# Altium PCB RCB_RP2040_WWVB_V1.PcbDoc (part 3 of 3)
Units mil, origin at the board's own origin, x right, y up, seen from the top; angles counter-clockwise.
Board outline 1250.1 x 2647.64 mil, 10 copper layers (L01-TOP, L02-GND, L03-SIG, L04-GND, L05-PWR, L06-PWR, L07-GND, L08-SIG, L09-GND, L10-BOT), stack 62.1 mil thick; 224 components, 123 nets, 635 pads, 542 vias.
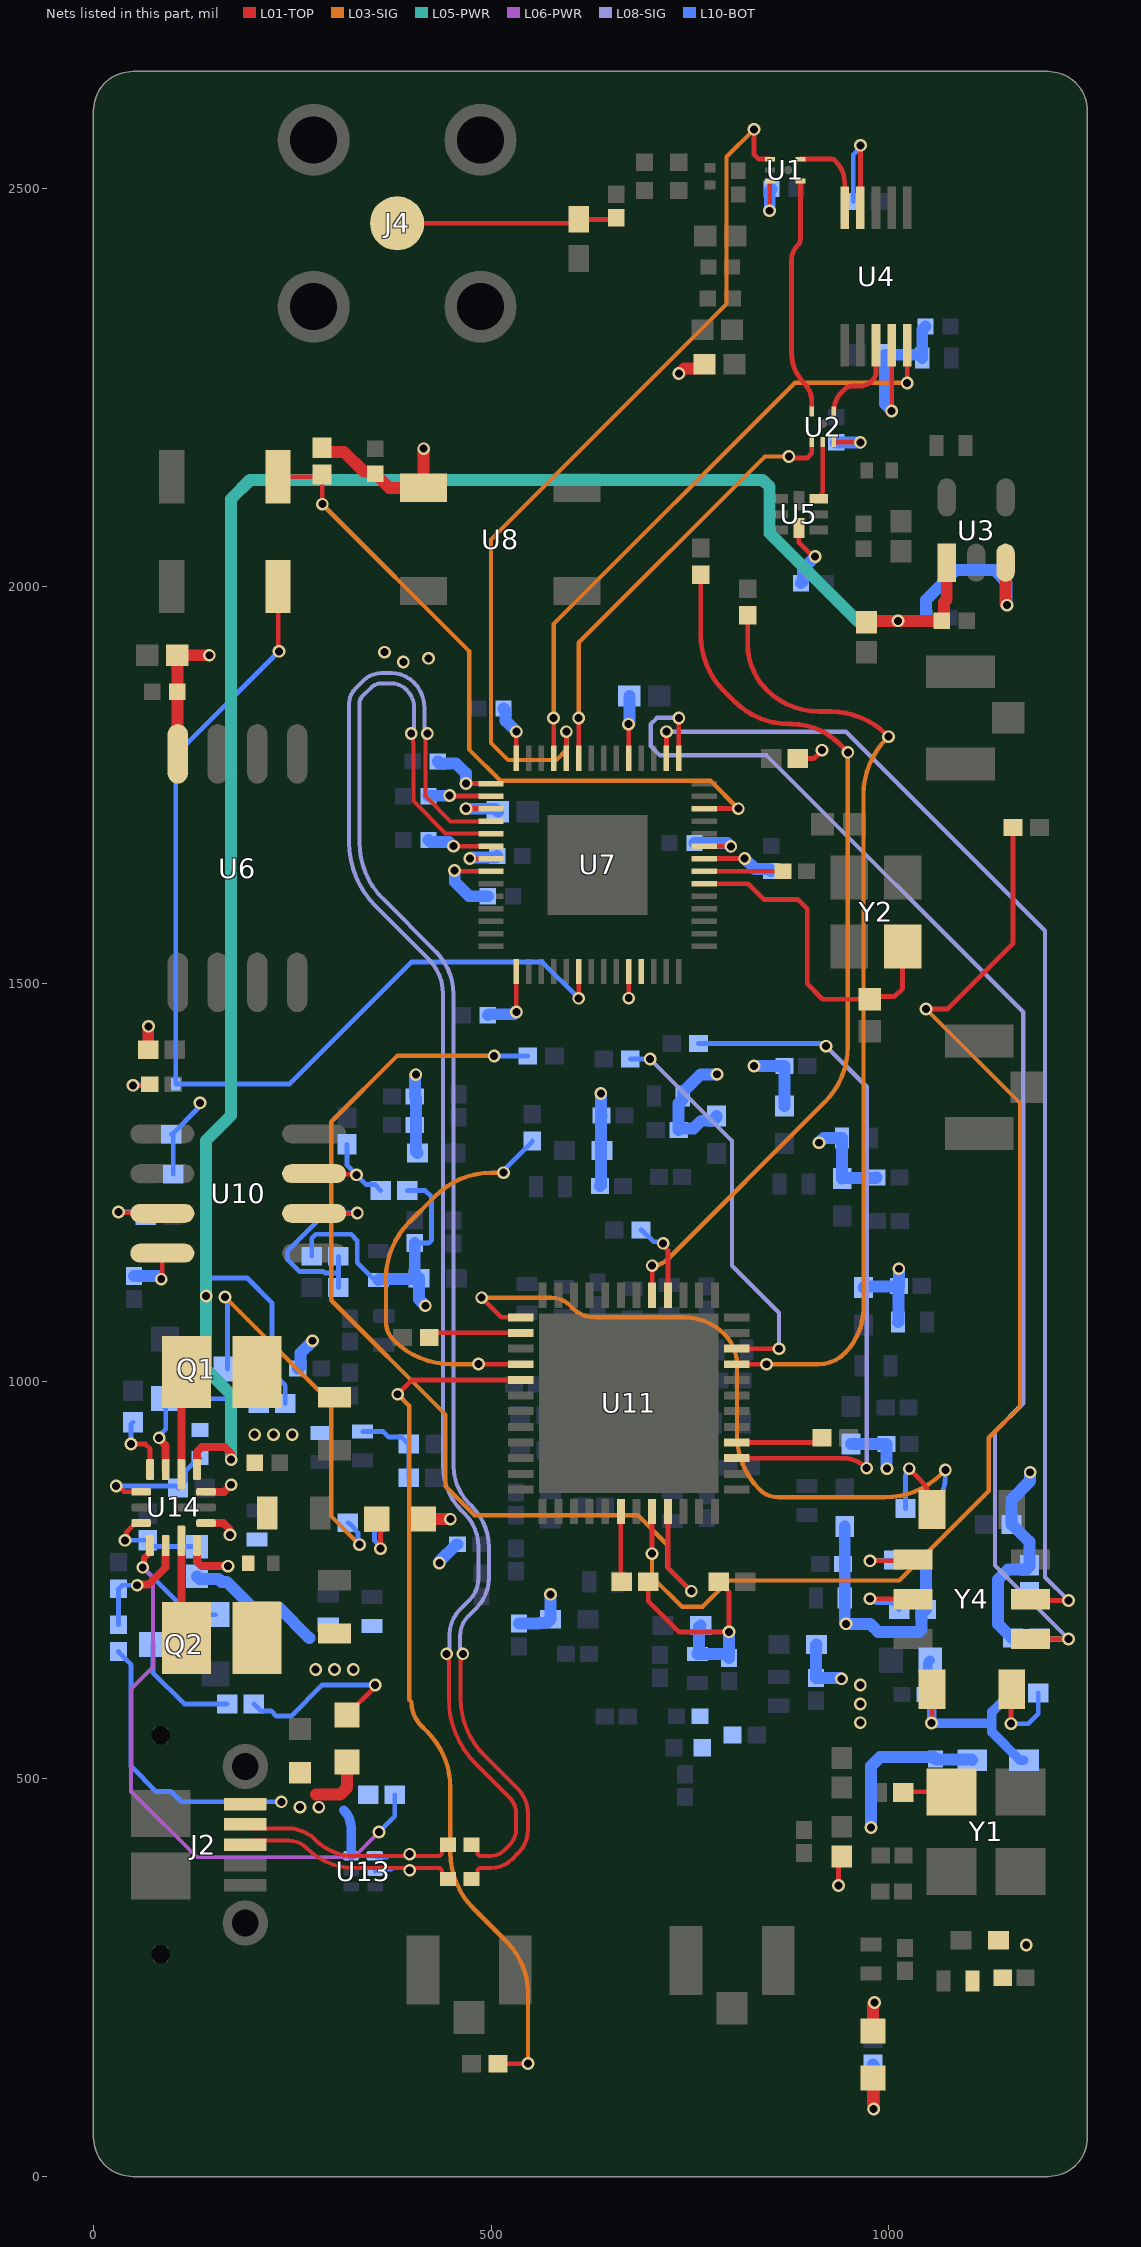
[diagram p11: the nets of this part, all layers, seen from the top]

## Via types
v1: diameter 16, hole 10, L01-TOP to L10-BOT, tented both sides, 542 vias

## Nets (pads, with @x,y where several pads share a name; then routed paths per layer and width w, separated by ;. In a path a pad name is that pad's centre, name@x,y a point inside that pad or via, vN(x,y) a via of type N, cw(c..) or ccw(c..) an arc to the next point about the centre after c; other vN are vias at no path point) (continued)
NetC56_1: C56.1 C57.2 FB2.1 R27.1 Y4.10 | length 319.9
  L01-TOP w6: v1(1054.1,570.39) 1054.72,571.02 Y4.10@1054.72,612.8
  L10-BOT w12: C56.1@1052.36,649.61 1049.15,646.39 1049.15,609.52 C57.2@1045.93,606.3 1047.24,606.3 1050.54,603 1050.54,601.68 1054.1,598.13 v1(1054.1,570.39) 1128.66,570.39 1129.92,571.66 ; R27.1@1154.72,608.07 1153.74,608.07 1129.92,584.26 1129.92,571.66 ; FB2.1@1170.28,523.62 1165.35,523.62 1129.92,559.06 1129.92,571.66
NetC61_2: C61.2 R47.1 R48.1
NetD1_1: D1.1 R71.2 | length 95.9
  L01-TOP w15: D1.1@980.31,124.02 980.31,85.83 v1(981.31,84.83)
  L10-BOT w15: R71.2@980.31,140.75 981.12,139.94 981.12,85.02 v1(981.31,84.83)
NetD2_2: D2.2 R10.1 | length 41
  L01-TOP w6: v1(49.58,1372.4) 69.25,1372.4 R10.1@70.87,1374.02
  L10-BOT w6: v1(49.58,1372.4) 50.39,1373.21 67.11,1373.21 D2.2@67.91,1374.02
NetD3_1: D3.1 R16.2 | length 74.5
  L01-TOP w6: D3.1@356.3,826.77 360.89,822.18 v1(360.89,789.73)
  L10-BOT w6: R16.2@353.35,822.18 353.35,799.98 360.89,792.44 v1(360.89,789.73)
NetD4_1: D4.1 R17.2 | length 227.1
  L01-TOP w5.5: D4.1@318.9,580.71 354.33,616.14 v1(354.33,618.11)
  L10-BOT w6: R17.2@201.77,594.49 210.58,585.68 223.52,585.68 230.01,579.19 248.48,579.19 287.4,618.11 v1(354.33,618.11)
NetL9_1: L9.1 U14.6 | length 125.3
  L01-TOP w10: U14.6@110.55,799.7 110.55,683.71 L9.1@117.1,677.17
NetL10_1: L10.1 U14.12 | length 119.3
  L01-TOP w10: U14.12@110.55,883.37 110.55,993.45 L10.1@117.1,1000
NetQ1_3: Q1.3 R16.1 | length 507.7
  L03-SIG w5.5: v1(165.35,1106.3) 299.21,972.44 299.21,830.13 v1(334.63,794.71)
  L10-BOT w6: v1(165.35,1106.3) 165.35,1103.59 168.54,1100.4 Q1.3@168.54,1015.75 ; R16.1@319.88,822.18 320.87,822.18 329.68,813.37 329.68,812.39 332.72,809.34 332.72,796.62 v1(334.63,794.71)
NetQ2_3: Q2.3 R17.1 | length 145.2
  L10-BOT w6: Q2.3@74.8,669.29 74.8,633.86 114.17,594.49 R17.1@168.31,594.49
NetR6_2: R6.2 U4.4 | length 152.4
  L01-TOP w6: U4.4@964.57,2476.51 964.57,2554.68 v1(964.61,2554.72)
  L10-BOT w6: R6.2@955.71,2484.25 955.71,2543.12 964.61,2552.02 v1(964.61,2554.72)
NetR7_1: R7.1 Y1.3 | length 61.3
  L01-TOP w6: R7.1@1018.43,482.91 1019.38,483.86 Y1.3@1079.29,483.86
NetR15_2: R15.2 R56.2 U14.3 | length 128.1
  L01-TOP w6: v1(39.71,800.2) 41.62,802.11 41.62,810.99 52.48,821.85 U14.3@59.86,821.85
  L10-BOT w6: v1(39.71,800.2) R56.2@68.24,800.2 76.16,792.28 R15.2@130.24,792.28
NetR20_1: R20.1 R30.1 U10.3 | length 135.7
  L01-TOP w6: U10.3@277.56,1261.42 278.35,1260.63 329.92,1260.63 v1(330.71,1259.84)
  L10-BOT w6: R30.1@318.9,1298.23 318.9,1272.07 330.71,1260.26 v1(330.71,1259.84) 342.73,1247.82 353.56,1247.82 R20.1@361.22,1240.16
NetR21_1: R21.1 R24.2 U10.2 | length 283.3
  L01-TOP w6: U10.2@277.56,1211.42 331.49,1211.42 v1(331.85,1211.78)
  L10-BOT w6: R24.2@308.07,1118.11 308.07,1136.32 ; R21.1@308.07,1157.48 308.07,1136.32 ; v1(331.85,1211.78) 291.7,1211.78 244.09,1164.17 244.09,1153.06 258.79,1138.37 289.28,1138.37 291.33,1136.32 308.07,1136.32
NetR25_2: R25.2 U10.7 | length 92
  L01-TOP w6: v1(31.53,1213.12) 32.39,1212.27 85.76,1212.27 U10.7@86.61,1211.42
  L10-BOT w6: v1(31.53,1213.12) 61.48,1213.12 R25.2@65.94,1208.66
NetR26_2: R26.2 Y4.6 | length 112
  L01-TOP w6: v1(1026.05,890.24) 1038.89,877.4 cw(c1000.66,839.17) Y4.6@1054.72,839.17
  L10-BOT w6: R26.2@1021.26,840.16 1021.26,878.67 cw(c1037.62,878.67) 1021.98,883.46 cw(c1037.62,878.67) v1(1026.05,890.24)
NetR27_2: R27.2 Y4.1 | length 109
  L01-TOP w6: v1(1154,569.6) 1154,612.07 Y4.1@1154.72,612.8
  L10-BOT w6: v1(1154,569.6) 1175.9,569.6 1188.19,581.89 R27.2@1188.19,608.07
NetR28_1: R28.1 Y4.7 | length 85.7
  L01-TOP w6: v1(976.6,774.46) 1029.38,774.46 Y4.7@1030.9,775.99
  L10-BOT w6: v1(976.6,774.46) 1005.76,774.46 R28.1@1006.89,775.59
NetR29_1: R29.1 Y4.8 | length 97.1
  L01-TOP w6: v1(976.6,726.71) 1030.18,726.71 Y4.8@1030.9,725.99
  L10-BOT w6: v1(976.6,726.71) 979.3,726.71 984.01,722 1004.69,722 R29.1@1013.5,713.19
NetR32_1: R32.1 U11.18 | length 88.8
  L01-TOP w6: U11.18@663.28,836.33 663.28,749.12 R32.1@664.37,748.03
NetR33_1: R33.1 U11.41 | length 1119.9
  L01-TOP w6: U11.41@702.76,1108.44 v1(702.76,1145.67) ; R33.1@763.78,2014.76 763.78,1939.06 ccw(c863.78,1939.06) 793.07,1868.35 805.36,1856.06 ccw(c876.07,1926.77) 876.07,1826.77 877.95,1826.77 cw(c877.95,1741.23) 938.44,1801.72 v1(948.82,1791.34)
  L03-SIG w5.5: v1(702.76,1145.67) ccw(c702.76,1173.21) 722.23,1153.74 919.53,1351.04 ccw(c848.82,1421.75) 948.82,1421.75 v1(948.82,1791.34)
NetR34_2: R34.2 U11.2 | length 116.6
  L01-TOP w6: R34.2@422.24,1055.12 cw(c437.02,1040.34) 437.02,1061.24 484.17,1061.24 484.28,1061.13 U11.2@537.12,1061.13
NetR35_1: R35.1 U11.33 | length 1199.5
  L01-TOP w6: U11.33@809.23,1021.65 v1(846.46,1021.65) ; R35.1@822.83,1963.58 822.83,1927.11 ccw(c903.49,1927.11) 846.46,1870.08 ccw(c912.99,1936.61) 912.99,1842.52 927.08,1842.52 cw(c927.08,1742.52) 997.79,1813.23 v1(1000,1811.02)
  L03-SIG w5.5: v1(846.46,1021.65) 911.61,1021.65 ccw(c911.61,1068.7) 944.88,1035.43 ccw(c887.85,1092.46) 968.5,1092.46 968.5,1738.11 cw(c1068.5,1738.11) 997.79,1808.82 v1(1000,1811.02)
NetR36_2: R36.2 U11.4 | length 521.5
  L01-TOP w6: v1(484.17,1021.87) 484.28,1021.76 U11.4@537.12,1021.76
  L03-SIG w5.5: v1(484.17,1021.87) 449.24,1021.87 cw(c449.24,1121.87) 378.53,1051.16 376.97,1052.71 cw(c398.85,1074.6) 367.9,1074.6 367.9,1129.63 cw(c467.9,1129.63) 397.19,1200.34 430.22,1233.37 cw(c500.93,1162.66) 500.93,1262.66 v1(515.75,1262.66)
  L10-BOT w6: v1(515.75,1262.66) 517.66,1264.57 517.66,1267.38 551.85,1301.57 R36.2@551.85,1302.55
NetR37_1: R37.1 U11.28 | length 112.5
  L01-TOP w6: U11.28@811.13,923.12 858.32,923.12 ; 863.97,923.12 858.32,923.12 ; R37.1@916.34,929.13 cw(c901.82,943.65) 901.82,923.12 858.32,923.12
NetR38_1: R38.1 U11.20 | length 1542.7
  L01-TOP w6: v1(702.54,783.38) 702.65,783.49 U11.20@702.65,836.33 ; v1(1047.24,1468.5) 1074.51,1468.5 1156.5,1550.49 R38.1@1156.5,1696.85
  L03-SIG w5.5: v1(702.54,783.38) 702.54,754.15 740.16,716.54 766.03,716.54 799.21,749.72 1013.5,749.72 1125.98,862.2 1125.98,929.13 1165.35,968.5 1165.35,1350.39 v1(1047.24,1468.5)
NetR39_1: R39.1 U11.40 | length 100.8
  L01-TOP w6: v1(716.54,1173.66) 716.54,1170.96 722.55,1164.94 U11.40@722.55,1110.34
  L10-BOT w6: R39.1@688.54,1190.47 689.52,1190.47 704.42,1175.58 714.62,1175.58 v1(716.54,1173.66)
NetR40_1: R40.1 U11.34 | length 509.5
  L01-TOP w6: U11.34@809.34,1041.23 862.18,1041.23 v1(862.29,1041.12)
  L08-SIG w5.5: v1(700.12,1405.56) 803.15,1302.53 803.15,1145.67 862.29,1086.53 v1(862.29,1041.12)
  L10-BOT w6: R40.1@675.2,1405.51 v1(700.12,1405.56) v1(700.12,1405.56)
NetR41_1: R41.1 U11.27 | length 878.6
  L01-TOP w6: U11.27@811.02,903.54 942.03,903.54 cw(c942.03,860.53) v1(972.44,890.95)
  L08-SIG w5.5: v1(921.26,1421.75) 972.44,1370.57 v1(972.44,890.95)
  L10-BOT w6: R41.1@760.83,1425.2 915.1,1425.2 918.55,1421.75 v1(921.26,1421.75)
NetR42_1: R42.1 U11.21 | length 1292.4
  L01-TOP w6: U11.21@722.44,836.44 722.44,765.75 v1(751.97,736.22)
  L03-SIG w5.5: v1(503.94,1409.45) 381.89,1409.45 299.05,1326.6 299.05,1102.08 442.78,958.35 442.78,868.25 479.27,831.75 684.82,831.75 722.44,794.13 722.44,765.75 v1(751.97,736.22)
  L10-BOT w6: v1(503.94,1409.45) R42.1@546.26,1409.45
NetR44_2: R44.2 U11.5 | length 1095.3
  L01-TOP w6: v1(382.59,983.89) 400.67,1001.97 U11.5@537.23,1001.97 ; R44.2@508.86,141.73 546.21,141.73 v1(546.51,142.04)
  L03-SIG w5.5: v1(382.59,983.89) 396.94,969.54 396.94,599.86 399.92,596.88 ccw(c442.28,596.88) 412.32,566.94 ; 412.33,566.93 419.64,559.62 cw(c348.93,488.91) 448.93,488.91 448.93,407.45 ccw(c548.93,407.45) 478.22,336.74 519.68,295.28 cw(c454.92,230.51) 546.51,230.51 v1(546.51,142.04)
NetR58_2: R58.2 R77.2 U14.1 | length 163.6
  L01-TOP w6: v1(28.54,868.44) 31.25,868.44 38.46,861.22 U14.1@59.86,861.22
  L10-BOT w6: v1(28.54,868.44) 104.01,868.44 R77.2@106.3,866.14 107.28,866.14 116.09,874.95 116.09,887.75 131.89,903.54 R58.2@133.86,903.54
NetR79_1: R79.1 R97.2 U14.5 | length 143.4
  L01-TOP w10: v1(55.01,743.71) 56.16,744.86 69.45,744.86 90.87,766.27 U14.5@90.87,793.8
  L10-BOT w6: R79.1@31.5,693.9 R97.2@31.5,739.17 36.03,743.71 v1(55.01,743.71)
NetR98_2: R98.2 U14.14 | length 81.2
  L01-TOP w6: v1(47.24,921.26) 65.38,921.26 71.18,915.46 U14.14@71.18,889.27
  L01-TOP w10: U14.14@71.1,889.35 U14.14@71.18,889.27
  L10-BOT w6: v1(47.24,921.26) 47.24,946.37 R98.2@49.69,948.82
P1V8: C42.1 C44.1 C48.2 C73.1 C74.1 C75.1 C79.1 C89.1 C99.1 C111.1 L4.1 L5.1 L7.1 L9.2 L12.1 L15.1 R15.1 R51.1 | length 668.9
  L10-BOT w15: R15.1@130.24,754.87 133.47,751.64 157.37,751.64 161.09,747.92 167.45,747.92 198.83,716.54 232.28,716.54 271.65,677.17 ; R51.1@256.89,1016.31 257.87,1016.31 260.22,1018.65 260.22,1035.54 275.59,1050.91 v1(275.59,1051.18) ; v1(405.51,1385.83) 405.51,1385.56 404.15,1384.2 C74.1@404.15,1358.27 405.85,1356.58 405.85,1289.09 L15.1@407.54,1287.4 ; v1(830.83,1396.83) 830.95,1396.72 C75.1@869.02,1396.72 ; L4.1@869.04,1346.59 C75.1@869.02,1396.72 ; L12.1@909.45,669.29 909.01,668.86 909.01,627.55 C99.1@908.58,627.12 939.81,627.12 v1(940.94,625.98) ; L7.1@952.76,921.43 952.79,921.39 997.23,921.39 C89.1@997.27,921.35 997.27,890.95 v1(997.98,890.24) ; L5.1@968.5,1118.11 969.6,1119.21 1011.9,1119.21 C79.1@1012.56,1119.87 ; C73.1@1012.13,1074.8 1012.56,1075.24 C79.1@1012.56,1119.87 ; v1(1012.99,1141.73) C79.1@1012.99,1120.31 C79.1@1012.56,1119.87
  other v1: 964.57,570.87 964.47,594.39 964.57,618.11 279.53,637.8 303.15,637.8 326.77,637.8
P1V8_PGOOD: Q2.1 R54.1 U14.4 | length 862.8
  L01-TOP w8: v1(61.98,766.27) 63.51,767.8 63.51,777.76 71.18,785.43 U14.4@71.18,793.8
  L06-PWR w5: v1(61.98,766.27) 74.8,753.44 74.8,640.83 47.24,613.27 47.24,484.25 129.92,401.57 327.47,401.57 v1(359.1,433.21)
  L10-BOT w6: v1(61.98,766.27) 110.55,717.69 110.55,714.39 118.25,706.69 Q2.1@153.54,706.69 ; v1(359.1,433.21) 378.94,453.04 R54.1@378.94,480.32
P3V3: C3.2 C7.2 C17.1 C18.1 C19.1 C20.1 C22.1 C23.1 C31.1 C32.1 C33.1 C34.1 C39.1 C40.1 C41.1 C43.1 C45.2 C46.1 C47.1 C49.1 C50.1 C51.1 C54.2 C55.1 C71.1 C72.1 C76.1 C86.1 C90.1 C91.1 C96.1 C100.1 C101.1 C104.1 C106.1 C112.1 C113.1 D1.2 FB2.2 L2.1 L3.1 L6.1 L8.1 L10.2 L11.1 L13.1 L14.1 L16.1 R3.2 R4.2 R9.1 R13.1 R18.1 R19.1 R20.2 R21.2 R22.1 R23.1 R28.2 R29.2 R31.2 R32.2 R49.2 R50.2 R52.1 R58.1 R95.2 R96.2 U1.6 U2.6 U4.9 U5.4 U6.8 U7.1 U7.10 U7.22 U7.33 U7.42 U7.43 U7.44 U7.48 U7.49 U8.1 U10.8 | length 3975.3
  L01-TOP w6: v1(85.24,1128.61) 86.61,1129.98 U10.8@86.61,1161.42 ; v1(447.96,1736.86) 448.6,1736.22 U7.44@500,1736.22 ; v1(452.76,1673.23) U7.48@500,1673.23 ; v1(468.5,1751.97) U7.43@500,1751.97 ; v1(473.38,1657.71) 473.61,1657.48 U7.49@500,1657.48 ; U7.42@531.64,1783.61 531.72,1783.69 531.72,1817.22 v1(531.81,1817.31) ; U7.1@531.75,1515.58 531.75,1464.68 v1(531.82,1464.61) ; v1(672.91,1826.76) 673.37,1826.3 U7.33@673.37,1783.61 ; v1(673.24,1482.09) 673.33,1482.18 U7.10@673.33,1515.7 ; R32.2@697.83,748.03 697.83,723.43 736.22,685.04 v1(799.21,685.04) 799.21,735.24 796.21,738.24 796.21,739.22 787.4,748.03 R22.1@786.42,748.03 ; U7.22@768.03,1657.59 818.92,1657.59 v1(819,1657.67) ; v1(850.39,2472.44) 850.69,2472.74 850.69,2509.8 850.74,2509.84 U1.6@850.98,2509.84 ; R31.2@885.83,1783.46 905.66,1783.46 v1(916.23,1794.03) ; U5.4@887.2,2073.43 887.2,2055.37 903.04,2039.54 905.79,2039.54 v1(907.7,2037.62) ; U2.6@931.1,2181.69 931.1,2181.51 931.15,2181.46 964.34,2181.46 v1(964.57,2181.24) ; v1(937.01,366.14) 937.01,398.62 R3.2@940.94,402.56 ; v1(1003.94,2220.47) U4.9@1003.94,2303.01
  L01-TOP w15: R9.1@68.9,1417.32 68.9,1446.3 v1(69.27,1446.67) ; U6.8@106.1,1789.37 105.78,1789.69 105.78,1913.06 C49.1@105.46,1913.39 v1(145.67,1913.39) ; R13.1@287.4,2174.21 287.4,2173.23 291.71,2168.92 315.33,2168.92 339.78,2144.47 351.59,2144.47 C51.1@354.33,2141.73 372.05,2124.02 U8.1@415.35,2124.02 v1(415.35,2173.23) ; v1(736.22,2267.72) 736.49,2267.72 743.01,2274.23 763.41,2274.23 R4.2@768.7,2279.53 ; D1.2@980.31,183.07 980.31,216.88 v1(982.3,218.87)
  L10-BOT w6: R19.1@100.32,1260.63 100.32,1308.65 R18.1@98,1310.97 98.98,1310.97 131.94,1343.94 131.94,1348.48 v1(133.86,1350.39) ; R21.2@274.61,1157.48 274.61,1180.12 279.53,1185.04 323.97,1185.04 331.85,1177.17 331.85,1149.45 353.84,1127.46 C71.1@358.27,1127.46 ; C41.1@338.58,937.01 364.4,937.01 371.33,930.07 387.84,930.07 R50.2@396.65,921.26 396.58,921.18 R49.2@396.58,878.76 ; R20.2@394.69,1240.16 417.32,1240.16 425.2,1232.28 425.2,1177.54 421.68,1174.03 C96.1@404.08,1174.03
  L10-BOT w15: C55.1@51.18,1132.5 81.09,1132.5 84.97,1128.61 v1(85.24,1128.61) ; C71.1@358.27,1127.46 359.5,1128.69 408.22,1128.69 L11.1@409.45,1129.92 ; C96.1@404.08,1174.03 404.08,1134.23 408.4,1129.92 L11.1@409.45,1129.92 ; v1(417.32,1095.24) 417.32,1095.51 409.45,1103.38 L11.1@409.45,1129.92 ; C39.1@421.26,1681.1 424,1678.37 447.35,1678.37 452.49,1673.23 v1(452.76,1673.23) ; C43.1@421.26,1736.22 421.71,1736.67 447.77,1736.67 v1(447.96,1736.86) ; C46.1@433.07,1779.87 435.81,1777.13 456.22,1777.13 468.31,1765.04 468.31,1752.16 v1(468.5,1751.97) ; v1(435.04,771.65) 435.23,771.84 435.23,773.81 456.69,795.28 R52.1@457.68,795.28 ; v1(473.38,1657.71) 473.65,1657.71 475.14,1659.19 506.09,1659.19 C34.1@507.87,1660.98 ; C33.1@496.06,1460.63 497.29,1461.86 528.8,1461.86 531.55,1464.61 v1(531.82,1464.61) ; C47.1@515.75,1846.46 518.48,1843.72 518.48,1830.91 531.81,1817.58 v1(531.81,1817.31) ; C76.1@535.43,695.49 560.23,695.49 561.21,696.48 570.49,696.48 L3.1@574.8,700.79 v1(574.8,732.28) ; C86.1@637.16,1246 638.16,1246.99 638.16,1333.65 C72.1@639.15,1334.65 638.35,1335.45 638.35,1362.01 v1(638.16,1362.2) ; v1(672.91,1826.76) 672.91,1827.03 674.07,1828.2 C31.1@674.07,1862.2 ; C100.1@741.17,1359.19 741.17,1354.76 736.02,1349.61 C101.1@736.02,1316.46 737.94,1318.38 754.95,1318.38 764.53,1327.95 779.41,1327.95 783.72,1332.26 L13.1@783.72,1333.74 ; C100.1@741.17,1363.62 763.76,1386.22 784.17,1386.22 v1(784.36,1386.41) ; C104.1@759.84,656.99 C104.1@760.45,656.99 ; L14.1@763.78,692.91 761.81,690.94 761.81,658.35 C104.1@760.45,656.99 ; C106.1@799.21,652.19 C106.1@799.21,653.54 ; v1(799.21,685.04) C106.1@799.21,653.54 ; v1(819,1657.67) 819.27,1657.67 832.28,1644.65 849.63,1644.65 C32.1@852.36,1641.92 ; v1(850.39,2472.44) 850.59,2472.63 850.59,2497.76 C3.2@852.83,2500 ; C20.1@889.76,2003.94 892.5,2006.67 892.5,2022.15 907.7,2037.35 v1(907.7,2037.62) ; v1(912.58,1300.22) 918.56,1306.2 C90.1@941.3,1306.2 941.49,1306 941.49,1255.61 L8.1@941.69,1255.42 942.18,1255.91 984.48,1255.91 C91.1@984.98,1256.41 ; C7.2@934.06,2181.24 v1(964.57,2181.24) ; C112.1@944.93,727.66 944.93,696.74 v1(946.57,695.09) 946.76,694.9 977.04,694.9 986.88,685.05 1038.18,685.05 1041.67,688.54 1041.67,708.88 1045.98,713.19 R29.2@1046.97,713.19 1046.97,769.96 1041.34,775.59 R28.2@1040.35,775.59 ; C112.1@944.93,727.66 L16.1@944.88,817.42 ; v1(978.05,439.06) 977.96,439.15 977.96,516.08 989.56,527.67 1057.25,527.67 1059.06,525.87 C54.2@1059.06,524.93 1059.71,524.27 1104.66,524.27 FB2.2@1105.31,523.62 ; v1(1003.94,2220.47) 1003.94,2220.74 995.22,2229.46 C18.1@995.22,2291.34 1041.06,2291.34 1042.42,2289.98 C19.1@1042.42,2287.4 1042.42,2322.83 C17.1@1046.36,2326.77 ; R95.2@1156.5,677.17 1155.51,677.17 1137.8,694.88 1137.8,751.06 1150.15,763.41 1172.85,763.41 1177.17,767.72 R96.2@1177.17,768.7 1177.17,798.57 1155.71,820.02 R23.1@1154.72,820.02 1154.72,851.58 1177.92,874.77 1177.92,885.64 v1(1178.11,885.83) ; C104.1@760.45,656.99 794.41,656.99 795.27,656.12 796.63,656.12 C106.1@799.21,653.54
  other v1: 1173.23,291.34 202.76,933.07 226.38,933.07 250,933.07 389.76,1905.02 421.26,1909.45 366.14,1917.32
P3V3_PGOOD: Q1.1 R53.1 U14.13 | length 204.5
  L01-TOP w10: v1(82.68,929.13) 82.68,927.51 90.87,919.32 U14.13@90.87,889.27
  L10-BOT w6: v1(82.68,929.13) 82.68,931.84 90.87,940.03 90.87,965.6 Q1.1@89.49,966.98 ; Q1.1@89.8,978.35 193.42,978.35 cw(c193.42,958.18) R53.1@207.68,972.44
RP2040_RST_N: R13.2 SW2.1 U7.26 | length 891.3
  L01-TOP w6: SW2.1@232.28,2137.8 284.45,2137.8 R13.2@287.4,2140.75 287.82,2140.33 v1(287.82,2103.43) ; U7.26@768,1720.47 v1(811.02,1720.47)
  L03-SIG w5.5: v1(287.82,2103.43) 472.44,1918.81 472.44,1794.87 511.84,1755.47 776.03,1755.47 v1(811.02,1720.47)
RP_CORE: C28.1 C29.1 C30.1 U7.23 U7.45 U7.50 | length 264.4
  L01-TOP w6: v1(454.2,1642.79) 455.25,1641.73 U7.50@500,1641.73 ; v1(468.5,1720.47) U7.45@500,1720.47 ; U7.23@768.04,1673.18 801.57,1673.18 v1(801.66,1673.1)
  L10-BOT w15: v1(454.2,1642.79) 454.39,1642.59 454.39,1628.29 472.44,1610.24 C29.1@496.06,1610.24 ; v1(468.5,1720.47) 468.7,1720.28 504.97,1720.28 C28.1@508.72,1716.54 ; C30.1@755.91,1677.17 797.32,1677.17 801.39,1673.1 v1(801.66,1673.1)
SiT5501_PLL_SCL: R96.1 U7.30 Y4.3 | length 1570.8
  L01-TOP w6: U7.30@720.66,1783.65 720.66,1817.18 v1(720.74,1817.27) ; Y4.3@1178.54,725.99 1180.12,724.41 v1(1226.33,724.41)
  L08-SIG w5.5: v1(720.74,1817.27) 946.51,1817.27 1196.85,1566.93 1196.85,753.88 v1(1226.33,724.41)
  L10-BOT w6: R96.1@1177.17,735.24 1177.17,734.25 1185.98,725.44 1186.96,725.44 1187.99,724.41 v1(1226.33,724.41)
SiT5501_PLL_SDA: R95.1 U7.29 Y4.2 | length 1650.5
  L01-TOP w6: v1(736.18,1834.6) 736.25,1834.53 U7.29@736.25,1783.63 ; Y4.2@1178.54,675.99 v1(1226.33,675.99)
  L08-SIG w5.5: v1(736.18,1834.6) 708.62,1834.6 700.79,1826.77 700.79,1799.21 712.6,1787.4 846.46,1787.4 1169.29,1464.57 1169.29,972.44 1133.86,937.01 1133.86,768.45 v1(1226.33,675.99)
  L10-BOT w6: R95.1@1189.96,677.17 1191.14,675.99 v1(1226.33,675.99)
TCXO_10M: R26.1 U11.1 | length 883.8
  L01-TOP w6: v1(488.19,1105.32) 512.8,1080.71 U11.1@537.23,1080.71
  L03-SIG w5.5: v1(488.19,1105.32) 575.66,1105.32 cw(c575.66,1071.84) 599.33,1095.51 602.75,1092.09 ccw(c630.48,1119.81) 630.48,1080.6 743.12,1080.6 cw(c743.12,1009.73) 793.23,1059.84 cw(c754.21,1020.83) 809.39,1020.83 809.39,932.58 ccw(c906.12,932.58) 837.72,864.17 ccw(c861.48,887.94) 861.48,854.33 995.65,854.33 ccw(c995.65,954.33) 1066.36,883.62 v1(1071.46,888.72)
  L10-BOT w6: R26.1@1054.72,840.16 ccw(c1014.33,880.55) 1071.46,880.55 v1(1071.46,888.72)
USB0_D_N: J2.2 R12.2 U13.1 | length 322.5
  L01-TOP w5: J2.2@190.96,442.9 ccw(c203.73,455.7) 203.73,437.62 251.64,437.62 257.5,436.02 cw(c245.43,391.1) 268.68,431.39 273.93,428.39 278.38,423.93 ccw(c329.25,474.79) 329.25,402.86 394.99,402.86 ccw(c394.99,405.51) v1(397.64,405.51) ccw(c402.72,410.59) 402.72,403.41 404.75,403.41 cw(c404.75,401.55) 406.07,402.86 418.97,402.86 419.28,403.17 433.52,403.17 ccw(c433.52,408.17) 437.06,404.63 ccw(c433.52,408.17) 438.52,408.17 438.52,408.53 cw(c444.4,408.53) 440.24,412.68 444.19,416.63 cw(c445.87,414.95) R12.2@445.87,417.32
  L10-BOT w5: U13.1@353.74,403.54 ccw(c359.1,408.91) 359.1,401.32 367.46,401.32 ccw(c367.46,403.95) 369.32,402.09 cw(c371.18,400.24) 371.18,402.86 394.99,402.86 ccw(c394.99,405.51) v1(397.64,405.51)
USB0_D_P: J2.3 R11.2 U13.2 | length 321.8
  L01-TOP w5: J2.3@190.94,417.32 cw(c203.73,404.54) 203.73,422.62 245.43,422.62 cw(c245.43,391.1) 267.72,413.39 267.78,413.32 ccw(c329.25,474.79) 329.25,387.86 394.99,387.86 cw(c394.99,385.21) v1(397.64,385.21) cw(c402.72,380.13) 402.72,387.32 404.75,387.32 ccw(c404.75,389.18) 406.07,387.86 425.18,387.86 425.49,388.17 433.52,388.17 cw(c433.52,383.17) 437.06,386.7 cw(c433.52,383.17) 438.52,383.17 438.52,382.81 ccw(c444.4,382.81) 440.24,378.65 444.19,374.71 ccw(c445.87,376.39) R11.2@445.87,374.02
  L10-BOT w5: U13.2@354.33,383.86 cw(c360.28,377.91) 360.28,386.32 373.67,386.32 ccw(c373.67,388.95) 375.53,387.09 cw(c377.39,385.24) 377.39,387.86 394.99,387.86 cw(c394.99,385.21) v1(397.64,385.21)
USB_BOOT: D2.1 SW1.1 U7.6 | length 1303.3
  L01-TOP w6: SW1.1@232.28,2000 232.28,1919.37 v1(233.35,1918.3) ; v1(610.25,1481.95) 610.33,1482.03 U7.6@610.33,1515.56
  L10-BOT w6: v1(233.35,1918.3) 103.35,1788.3 D2.1@103.35,1374.02 246.06,1374.02 399.61,1527.56 564.64,1527.56 v1(610.25,1481.95)
USB_R_N: R12.1 U7.46 | length 1943.1
  L01-TOP w5: v1(419.97,1814.96) 417.87,1812.86 417.87,1803.69 417.32,1803.15 417.32,1736.22 449.19,1704.35 499.63,1704.35 U7.46@500,1704.72 ; v1(444.27,657.48) cw(c439.19,652.4) 446.37,652.4 446.37,650.37 ccw(c448.23,650.37) 446.92,649.05 446.92,600.72 ccw(c561.92,600.72) 480.6,519.4 523.14,476.86 cw(c502.98,456.69) 531.5,456.69 531.5,436.33 cw(c504.61,436.33) 523.62,417.32 516.16,409.86 cw(c500,426.03) 500,403.17 487.74,403.17 cw(c487.74,408.17) 484.2,404.63 cw(c487.74,408.17) 482.74,408.17 482.74,408.53 ccw(c476.86,408.53) 481.02,412.68 477.07,416.63 ccw(c475.39,414.95) R12.1@475.39,417.32
  L08-SIG w5: v1(419.97,1814.96) 419.97,1815.36 ccw(c413.74,1815.36) 418.15,1819.76 cw(c422.55,1824.17) 416.32,1824.17 416.32,1846.85 ccw(c370.47,1846.85) 402.89,1879.27 ccw(c374.69,1851.07) 374.69,1890.95 362.2,1890.95 ccw(c362.2,1858.94) 339.57,1881.58 329.39,1871.4 ccw(c348.09,1852.7) 321.65,1852.7 321.65,1677.92 ccw(c434.65,1677.92) 354.74,1598.01 421.26,1531.5 cw(c376.61,1486.84) 439.76,1486.84 439.76,893.98 ccw(c519.96,893.98) 463.25,837.26 ; v1(444.27,657.48) 444.27,657.88 cw(c450.5,657.88) 446.09,662.28 ccw(c441.69,666.69) 447.92,666.69 447.92,682 cw(c491.11,682) 460.57,712.53 472.44,724.41 ccw(c443.93,752.92) 484.25,752.92 484.25,791.34 ccw(c424.08,791.34) 466.63,833.88 463.25,837.26
USB_R_P: R11.1 U7.47 | length 1950.4
  L01-TOP w5: v1(399.67,1814.96) 401.78,1812.86 401.78,1803.69 402.32,1803.15 402.32,1730.01 442.98,1689.35 499.63,1689.35 U7.47@500,1688.98 ; v1(464.57,657.48) ccw(c469.65,652.4) 462.46,652.4 462.46,650.37 cw(c460.6,650.37) 461.92,649.05 461.92,600.72 ccw(c561.92,600.72) 491.21,530.01 533.75,487.46 cw(c502.98,456.69) 546.5,456.69 546.5,436.33 cw(c504.61,436.33) 534.23,406.72 526.77,399.26 cw(c500,426.03) 500,388.17 487.74,388.17 ccw(c487.74,383.17) 484.2,386.7 ccw(c487.74,383.17) 482.74,383.17 482.74,382.81 cw(c476.86,382.81) 481.02,378.65 477.07,374.71 cw(c475.39,376.39) R11.1@475.39,374.02
  L08-SIG w5: v1(399.67,1814.96) 399.67,1815.36 cw(c405.9,1815.36) 401.5,1819.76 ccw(c397.09,1824.17) 403.32,1824.17 403.32,1846.85 ccw(c370.47,1846.85) 393.7,1870.08 ccw(c374.69,1851.07) 374.69,1877.95 362.2,1877.95 ccw(c362.2,1858.94) 348.76,1872.39 338.58,1862.2 ccw(c348.09,1852.7) 334.65,1852.7 334.65,1677.92 ccw(c434.65,1677.92) 363.94,1607.21 430.45,1540.69 cw(c376.61,1486.84) 452.76,1486.84 452.76,893.98 ccw(c519.96,893.98) 472.44,846.46 475.82,843.08 cw(c424.08,791.34) 497.25,791.34 497.25,752.92 cw(c443.93,752.92) 481.63,715.22 471.66,705.25 ccw(c497.61,679.3) 460.92,679.3 460.92,666.69 ccw(c467.15,666.69) 462.74,662.28 cw(c458.34,657.88) 464.57,657.88 v1(464.57,657.48)
VBUS_USB: C1.1 C9.1 C10.1 C11.1 C12.1 C35.1 C36.1 C37.1 C38.2 C105.1 D3.2 D4.2 J2.1 R53.2 R54.2 R79.2 U3.1 U3.3 U13.6 U14.7 U14.8 U14.10 U14.11 | length 3653
  L01-TOP w10: U14.7@130.24,793.8 130.24,773.57 136.09,767.72 v1(169.29,767.72) ; U14.11@130.24,889.27 130.24,911.46 136.09,917.32 165.35,917.32 173.23,909.45 v1(173.23,901.57) ; U14.8@141.56,821.85 141.63,821.77 163.59,821.77 171.38,813.98 171.38,807.52 v1(171.81,807.09) ; U14.10@141.56,861.22 164.37,861.22 v1(173.23,870.08)
  L01-TOP w15: 279.53,480.31 310.11,480.31 318.9,489.1 D4.2@318.9,521.65 ; D3.2@415.36,826.77 v1(448.82,826.77) ; C11.1@972.44,1955 973.94,1956.5 1011.62,1956.5 v1(1011.81,1956.69) C12.1@1066.93,1956.69 1069.67,1959.43 1069.67,1979.7 1073.25,1983.29 U3.1@1073.25,2029.79 ; U3.3@1147.22,2029.79 1147.22,1978.08 v1(1148.89,1976.42)
  L05-PWR w15: v1(173.23,901.57) 173.23,983.51 141.73,1015.01 v1(141.73,1107.44) 141.73,1303.15 173.23,1334.65 173.23,2110.24 196.85,2133.86 841.61,2133.86 850.39,2125.07 850.39,2066.93 960.63,1956.69 v1(1011.81,1956.69)
  L10-BOT w6: R79.2@31.5,660.43 31.5,659.45 47.24,643.7 47.24,515.75 78.74,484.25 97.72,484.25 110.68,471.29 v1(236.22,471.29) ; v1(141.73,1107.44) 141.73,1124.42 147.43,1130.12 193.13,1130.12 224.41,1098.83 224.41,1012.07 241.14,995.33 R53.2@241.14,972.44
  L10-BOT w12: 314.96,460.63 cw(c293.09,438.76) 324.02,438.76 U13.6@324.02,403.54
  L10-BOT w15: C9.1@972.44,1955.22 973.8,1956.57 981.19,1956.57 981.31,1956.69 v1(1011.81,1956.69) C10.1@1043.31,1956.69 ; C10.1@1047.24,1960.63 1047.24,1983.15 1084.83,2020.73 1132.81,2020.73 1148.7,2004.85 1148.7,1976.61 v1(1148.89,1976.42)
  other v1: 259.84,464.57 283.46,464.57
WWVB_ADC_IN: U2.5 U5.7 | length 72.8
  L01-TOP w6: U5.7@912.2,2110.24 ccw(c899.85,2122.59) 917.32,2122.59 U2.5@917.32,2181.69
WWVB_AMP0_OUT: U2.1 U4.8 | length 115.5
  L01-TOP w6: U2.1@931.1,2219.88 cw(c965.79,2219.88) 941.26,2244.41 944.88,2248.03 cw(c954.39,2238.53) 954.39,2251.97 964.57,2251.97 ccw(c964.57,2270.98) 978.01,2257.54 980.31,2259.84 ccw(c970.81,2269.35) 984.25,2269.35 U4.8@984.25,2303.01
WWVB_AMP_CS0: U4.10 U7.39 | length 786.6
  L01-TOP w6: v1(578.7,1834.6) 578.77,1834.53 U7.39@578.77,1783.63 ; v1(1023.48,2255.92) 1023.62,2256.06 U4.10@1023.62,2303.01
  L03-SIG w5.5: v1(578.7,1834.6) 578.7,1952.71 881.9,2255.92 v1(1023.48,2255.92)
WWVB_AMP_IN: U1.3 U4.5 | length 106.5
  L01-TOP w6: U1.3@889.17,2537.4 928.32,2537.4 cw(c928.32,2530.68) 933.07,2535.43 cw(c904.56,2506.92) 944.88,2506.92 U4.5@944.88,2476.51
WWVB_ANT_SEL: U7.11
WWVB_DIRECT_IN: U1.1 U2.3 | length 299.8
  L01-TOP w6: U1.1@889.17,2509.84 889.17,2437.21 cw(c877.75,2437.21) 885.83,2429.13 ccw(c904.84,2410.12) 877.95,2410.12 877.95,2293.92 ccw(c931.72,2293.92) 893.7,2255.91 cw(c869.94,2232.14) 903.54,2232.14 U2.3@903.54,2219.88
WWVB_RF_IN: C2.1 D5.2 J4.1 | length 278.4
  L01-TOP w6: J4.1@381.89,2456.69 605.31,2456.69 D5.2@610.24,2461.61 655.71,2461.61 C2.1@657.48,2463.39
WWVB_RF_SW2_CTRL: U2.4 U7.37 | length 553.5
  L01-TOP w6: v1(610.19,1834.6) 610.26,1834.53 U7.37@610.26,1783.63 ; v1(874.57,2163.37) 876.52,2161.42 897.64,2161.42 903.54,2167.32 U2.4@903.54,2181.69
  L03-SIG w5.5: v1(610.19,1834.6) 610.19,1929.09 844.47,2163.37 v1(874.57,2163.37)
WWVB_RF_SW_CTRL: U1.4 U7.38 | length 1128.6
  L01-TOP w6: U7.38@594.67,1783.65 594.67,1817.18 v1(594.76,1817.27) ; v1(830.71,2574.8) 830.71,2543.31 836.61,2537.4 U1.4@850.98,2537.4
  L03-SIG w5.5: v1(594.76,1817.27) 594.76,1794.01 582.38,1781.63 521.52,1781.63 500,1803.15 500,2059.06 796.26,2355.31 796.26,2540.35 v1(830.71,2574.8)
XIN: C52.2 U7.20 Y2.1 | length 423.9
  L01-TOP w6: U7.20@768,1625.98 823.32,1625.98 843.01,1606.3 885.83,1606.3 897.64,1594.49 897.64,1500 916.93,1480.71 C52.2@976.38,1480.71 979.92,1484.25 1007.87,1484.25 1017.72,1494.09 Y2.1@1017.72,1547.24
XOUT: R14.2 U7.21 | length 99.1
  L01-TOP w6: U7.21@768,1641.73 R14.2@867.13,1641.73
pads on no net: J2.4 U3.4 U4.6 U4.7 U7.24 U7.25 U7.31 U7.32 U7.34 U7.35 U7.36 U8.2 U10.1 U11.44 U13.4 U13.5 Y1.1 Y4.4 Y4.9

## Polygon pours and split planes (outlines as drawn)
ADC_AVDD on L01-TOP "NONET_L-01_P-001" (solid, pour order 122): 1084.83,2117.08 1084.83,2138.1 1069.39,2153.54 1069.39,2187.4 1018.11,2187.4 996.06,2165.35 996.06,2118.11 973.42,2095.47 908.67,2095.47 908.48,2095.28 899.85,2095.28 899.85,2086.57 900.79,2085.63 941.14,2085.63 958.27,2068.5 1028.23,2068.5 1028.99,2067.75 1056.97,2095.73 1084.2,2095.73
GND on L01-TOP "NONET_L-01_P-001" (solid, pour order 124): -133.86,2712.6 1374.02,2712.6 1374.02,-94.49 -125.98,-94.49 -125.98,291.34
NetC24_1 on L01-TOP "NONET_L-01_P-001" (solid, pour order 101): 1104.39,347.93 1110.79,354.33 1110.79,413.39 1110.55,413.62 1007.44,413.62 1007.44,393.46 1006.89,392.91 1006.89,348.19 964.43,305.73 964.43,283.11 991,283.11 998,276.11 1095.07,276.11 1104.39,285.43
P3V3 on L01-TOP "NONET_L-01_P-001" (solid, pour order 100): 1155.08,239.92 1155.08,262.79 1163.94,271.65 1174.02,271.65 1187.8,285.43 1187.8,302.36 1181.1,309.06 1125.06,309.06 1125.06,285.43 1096.52,256.89 1096.52,235.25 1099,232.78 1147.94,232.78
P3V3 on L01-TOP "NONET_L-01_P-001" (solid, pour order 91): 236.34,1024.12 236.34,1057.21 175.13,1057.21 175.13,942.98 196.85,921.26 256.89,921.26 261.81,926.18 261.81,946.85 282.48,967.52 323.82,967.52 323.82,1024.12
P1V8 on L01-TOP "NONET_L-01_P-001" (solid, pour order 90): 263.04,695.87 236.34,722.56 175.13,722.56 175.13,631.77 188.78,618.11 326.77,618.11 338.58,629.92 338.58,660.69 323.82,675.45 323.82,695.87
VBUS_USB on L01-TOP "NONET_L-01_P-001" (solid, pour order 88): 151.89,867.44 166.34,881.89 204.72,881.89 231.3,855.31 231.3,813.98 202.49,785.16 202.49,761.3 190.44,749.25 147.72,749.25 133.19,763.78 133.19,771.83 145.5,784.14 153.86,784.14 157.8,788.08 157.8,827.91 185.19,827.91 187.99,830.71 187.99,850.18 181.88,856.3 151.89,856.3
VBUS_USB on L01-TOP "NONET_L-01_P-001" (solid, pour order 87): 212.99,907.87 186.61,907.87 170.7,923.79 136.94,923.79 125.32,912.16 125.32,906.5 144.41,887.4 212.99,887.4
VBUS_USB on L01-TOP "NONET_L-01_P-001" (solid, pour order 82): 210.63,476.38 228.35,494.09 228.35,503.94 246.06,521.65 273.62,521.65 291.34,503.94 291.34,456.69 283.46,448.82 229.33,448.82 217.52,460.63 164.37,460.63 164.37,474.41 164.37,476.38
GND on L07-GND "NONET_L-01_P-001" (solid, pour order 120): -165.35,2724.41 1476.38,2724.41 1476.38,-129.92 -192.91,-129.92 -192.91,452.76
GND on L02-GND "NONET_L-01_P-001" (solid, pour order 119): -165.35,2724.41 1476.38,2724.41 1476.38,-129.92 -192.91,-129.92 -192.91,452.76
P3V3 on L06-PWR "NONET_L-01_P-001" (solid, pour order 126): 338.58,2086.61 1000,2086.61 1000,1657.48 849.27,1506.75 460.84,1506.75 338.58,1629.01
P3V3 on L06-PWR "NONET_L-01_P-001" (solid, remove dead copper, pour order 102): -7.87,1472.44 1259.84,1472.44 1322.83,1409.45 1322.83,66.93 1224.41,-31.5 11.81,-31.5 -35.43,15.75
P1V8 on L06-PWR "NONET_L-01_P-001" (solid, pour order 84): 275.59,1035.43 259.84,1051.18 259.84,1248.03 377.07,1365.26 476.51,1365.26 668.39,1173.38 668.39,1035.43 429.13,1035.43
P1V8 on L06-PWR "NONET_L-01_P-001" (solid, pour order 98): 795.53,1341.72 634.1,1341.72 551.47,1424.35 400.73,1424.35 377.95,1401.57 377.95,1350.39 631.48,1096.87 822.83,1096.87
P1V8 on L06-PWR "NONET_L-01_P-001" (solid, pour order 97): 814.96,1421.26 787.66,1393.95 787.66,1068.26 870.08,985.83 870.08,584.26 951.39,502.95 1113.19,502.95 1145.67,535.43 1145.67,1106.3 1094.49,1157.48 960.63,1157.48 937.01,1181.1 937.01,1358.27 874.02,1421.26
VBUS_USB on L06-PWR "NONET_L-01_P-001" (solid, remove dead copper, pour order 96): 307.09,374.02 480.31,547.24 480.31,883.83 201.2,1162.95 56.65,1162.95 31.5,1137.8 31.5,460.63 118.11,374.02
P3V3 on L10-BOT "NONET_L-01_P-001" (solid, pour order 85): 477.36,1399.12 499.33,1377.15 530,1377.15 530,1403.07 497.05,1436.02 497.05,1448.46 477.36,1448.46
GND on L10-BOT "NONET_L-01_P-001" (solid, pour order 123): -110.24,1897.64 -110.24,2740.16 1397.64,2740.16 1397.64,-137.8 -90.55,-137.8 -90.55,303.15
NetC61_2 on L10-BOT "NONET_L-01_P-001" (solid, pour order 109): 751.97,588.58 792.13,588.58 814.96,565.75 814.96,545.98 797.52,528.54 754.92,528.54 754.92,565.94 751.97,568.9
DPLL_FILTER on L10-BOT "NONET_L-01_P-001" (solid, pour order 105): 660.43,588.82 670.04,598.43 734.25,598.43 744.09,588.58 744.09,553.15 741.14,550.2 741.14,530.54 754.18,517.51 754.18,494.63 720.1,494.63 683.31,531.42 683.31,545.78 660.43,568.66
P1V8 on L10-BOT "NONET_L-01_P-001" (solid, pour order 103): 363.68,651.08 338.58,625.98 267.72,625.98 249.69,644.01 249.69,685.53 267.41,703.25 308.56,703.25 310.53,701.28 361.53,701.28 363.68,699.13
P3V3 on L10-BOT "NONET_L-01_P-001" (solid, pour order 94): 148.74,926.06 144.69,930.12 123.03,930.12 123.03,957.4 132.05,966.41 293.43,966.41 303.15,956.69 341.04,956.69 351.87,945.87 351.87,928.15 301.8,928.15 299.7,926.06
VBUS_USB on L10-BOT "NONET_L-01_P-001" (solid, pour order 93): 237.2,512.8 272.64,512.8 290.19,530.35 290.19,542.4 343.43,542.4 354.33,531.5 354.33,468.5 330.71,444.88 233.27,444.88 223.43,454.72 223.43,482.77 236.22,495.56
VBUS_USB on L10-BOT "NONET_L-01_P-001" (solid, pour order 89): 182.58,810.05 173.23,819.4 160.56,819.4 157.8,816.63 157.8,751.65 165.35,744.09 208.68,744.09 219,754.41 219,810.05
VBUS_USB on L10-BOT "NONET_L-01_P-001" (solid, pour order 86): 210.63,907.48 200.79,917.32 171.26,917.32 161.42,907.48 161.42,866.14 169.29,858.27 206.69,858.27 210.63,862.2 210.63,891.88
RP_CORE on L05-PWR "NONET_L-01_P-001" (solid, pour order 106): 381.89,1637.8 381.89,1720.47 430.2,1768.79 752.67,1768.79 789.17,1732.28 826.77,1732.28 842.13,1716.93 842.13,1643.75 823.84,1625.46 578.22,1625.46 551.18,1598.43 417.32,1598.43 387.52,1628.23
DPLL_FILTER on L05-PWR "NONET_L-01_P-001" (solid, pour order 107): 559.96,825.61 559.96,778.89 608.63,730.22 608.63,551.42 631.51,528.54 756.14,528.54 783.46,555.86 783.46,753.27 715.06,821.67
P1V8 on L05-PWR "L05-PWR-P1V8" (solid, pour order 108): 243.31,400.08 320.56,322.83 847.88,322.83 928.15,403.11 928.15,460.63 1090.55,460.63 1122.05,492.13 1122.05,669.29 236.22,669.29 215.47,648.54 215.47,460.63 243.31,460.63
P3V3 on L05-PWR "NONET_L-01_P-001" (solid, pour order 125): 35.43,968.5 35.43,2598.43 70.87,2633.86 1181.1,2633.86 1236.22,2578.74 1236.22,43.31 1216.54,23.62 59.06,23.62 27.56,55.12
GND on L04-GND "NONET_L-01_P-001" (solid, pour order 83): -165.35,2724.41 1476.38,2724.41 1476.38,-129.92 -192.91,-129.92 -192.91,452.76
GND on L09-GND "NONET_L-01_P-001" (solid, pour order 121): -165.35,2724.41 1476.38,2724.41 1476.38,-129.92 -192.91,-129.92 -192.91,452.76

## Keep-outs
Keep-Out Layer:
  lines w0.5: 2379.06,-1421.42 ccw(c2379.02,-1381.3) 2419.13,-1381.3

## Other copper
L01-TOP:
  pour cut-out: 125.32,906.5 144.41,906.5 144.41,887.4 125.32,887.4 125.32,889.27
  pour cut-out: 125.98,771.65 157.8,771.65 157.8,788.56 125.32,788.56

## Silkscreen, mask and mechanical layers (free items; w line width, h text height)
Top Overlay:
  lines w10: 283.46,75.29 919.53,75.29 919.53,385.83 283.46,385.83 283.46,75.29
  text "RCB Header in future" at 366.17,87.26 h60
Board Layer Stack Bottom Overlay:
  drawing of 9 lines, arcs and shapes, not listed
  text "RCB RP2040 WWVB V1 / Julian St. James / Ahmad Byagowi" at 936.22,2104.72 h59.06
Board Shape:
  circle w10: c1136.81,2514.76 r61.02
  circle w10: c113.19,2514.76 r61.02
  circle w10: c113.19,132.87 r61.02
  circle w10: c1136.81,132.87 r61.02
  lines w10: 1200.69,2647.64 cw(c1200.69,2598.33) 1250,2598.33 1250,49.31 ; 1200.79,2647.64 49.31,2647.64 ccw(c49.31,2598.33) 0,2598.33 0,49.31 ccw(c49.31,49.31) 49.31,0 1200.79,0 ccw(c1200.79,49.31) 1250.1,49.31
